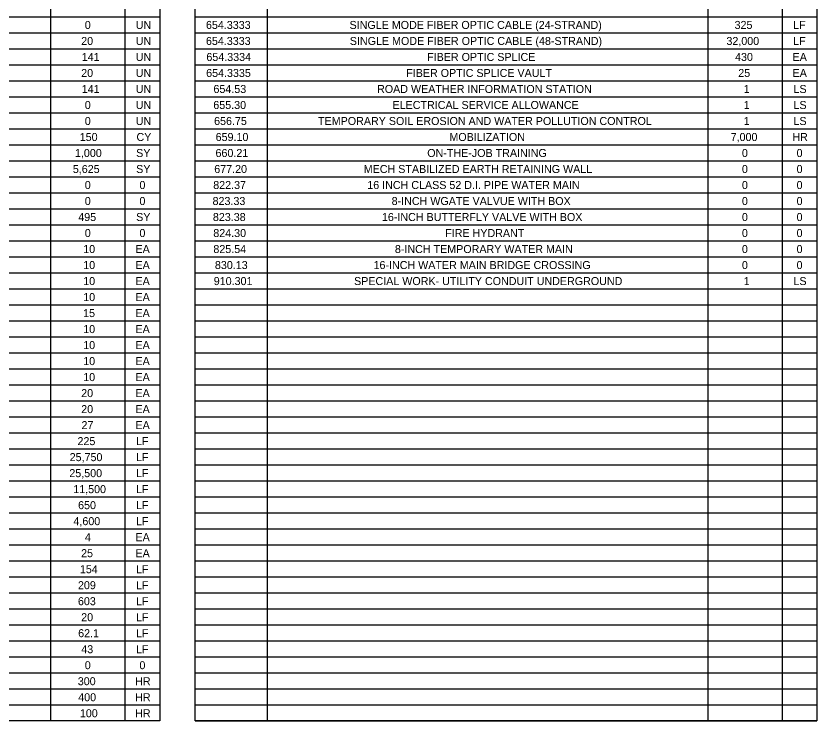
# Model space of a CAD drawing. Extents: x -18.7 to 5.6, y -2.7 to 5.1.
# Drawn here: x 4.632 to 5.617, y 0.019 to 0.886 of the extents above; entities that cross this region are included whole.
import ezdxf

# ---------------------------------------------------------------- set-up
doc = ezdxf.new("R2010")
doc.units = 0
doc.layers.add('ANNOTATION', color=7, linetype='Continuous')
doc.layers.add('BORDER', color=7, linetype='Continuous')

msp = doc.modelspace()

# ---------------------------------------------------------------- linework, layer by layer
at = {"layer": 'BORDER'}
for p, q in [((4.67472, 1.73155), (4.67472, 0.01886)), ((4.76611, 1.73155), (4.76611, 0.01886)), ((4.94124, 1.73155), (4.94124, 0.01886)), ((5.48258, 1.73155), (5.48258, 0.01886)), ((5.57397, 1.73155), (5.57397, 0.01886)), ((3.9448, 0.88505), (4.8091, 0.88505)), ((4.85265, 0.88505), (5.61696, 0.88505)), ((3.9448, 0.86536), (4.8091, 0.86536)), ((4.85265, 0.86536), (5.61696, 0.86536)), ((3.9448, 0.84568), (4.8091, 0.84568)), ((4.85265, 0.84568), (5.61696, 0.84568)), ((3.9448, 0.82599), (4.8091, 0.82599)), ((4.85265, 0.82599), (5.61696, 0.82599)), ((3.9448, 0.8063), (4.8091, 0.8063)), ((4.85265, 0.8063), (5.61696, 0.8063)), ((3.9448, 0.78662), (4.8091, 0.78662)), ((4.85265, 0.78662), (5.61696, 0.78662)), ((3.9448, 0.76693), (4.8091, 0.76693)), ((4.85265, 0.76693), (5.61696, 0.76693)), ((3.9448, 0.74725), (4.8091, 0.74725)), ((4.85265, 0.74725), (5.61696, 0.74725)), ((3.9448, 0.72756), (4.8091, 0.72756)), ((4.85265, 0.72756), (5.61696, 0.72756)), ((3.9448, 0.70787), (4.8091, 0.70787)), ((4.85265, 0.70787), (5.61696, 0.70787)), ((3.9448, 0.68819), (4.8091, 0.68819)), ((4.85265, 0.68819), (5.61696, 0.68819)), ((3.9448, 0.6685), (4.8091, 0.6685)), ((4.85265, 0.6685), (5.61696, 0.6685)), ((3.9448, 0.64882), (4.8091, 0.64882)), ((4.85265, 0.64882), (5.61696, 0.64882)), ((3.9448, 0.62913), (4.8091, 0.62913)), ((4.85265, 0.62913), (5.61696, 0.62913)), ((3.9448, 0.60944), (4.8091, 0.60944)), ((4.85265, 0.60944), (5.61696, 0.60944)), ((3.9448, 0.58976), (4.8091, 0.58976)), ((4.85265, 0.58976), (5.61696, 0.58976)), ((3.9448, 0.57007), (4.8091, 0.57007)), ((4.85265, 0.57007), (5.61696, 0.57007)), ((3.9448, 0.55039), (4.8091, 0.55039)), ((4.85265, 0.55039), (5.61696, 0.55039)), ((3.9448, 0.5307), (4.8091, 0.5307)), ((4.85265, 0.5307), (5.61696, 0.5307)), ((3.9448, 0.51101), (4.8091, 0.51101)), ((4.85265, 0.51101), (5.61696, 0.51101)), ((3.9448, 0.49133), (4.8091, 0.49133)), ((4.85265, 0.49133), (5.61696, 0.49133)), ((3.9448, 0.47164), (4.8091, 0.47164)), ((4.85265, 0.47164), (5.61696, 0.47164)), ((3.97991, 0.45196), (4.8091, 0.45196)), ((4.85265, 0.45196), (5.61696, 0.45196)), ((3.9448, 0.43227), (4.8091, 0.43227)), ((4.85265, 0.43227), (5.61696, 0.43227)), ((3.9448, 0.41258), (4.8091, 0.41258)), ((4.85265, 0.41258), (5.61696, 0.41258)), ((3.9448, 0.3929), (4.8091, 0.3929)), ((4.85265, 0.3929), (5.61696, 0.3929)), ((3.9448, 0.37321), (4.8091, 0.37321)), ((4.85265, 0.37321), (5.61696, 0.37321)), ((3.9448, 0.35353), (4.8091, 0.35353)), ((4.85265, 0.35353), (5.61696, 0.35353)), ((3.9448, 0.33384), (4.8091, 0.33384)), ((4.85265, 0.33384), (5.61696, 0.33384)), ((3.9448, 0.31415), (4.8091, 0.31415)), ((4.85265, 0.31415), (5.61696, 0.31415)), ((3.9448, 0.29447), (4.8091, 0.29447)), ((4.85265, 0.29447), (5.61696, 0.29447)), ((3.9448, 0.27478), (4.8091, 0.27478)), ((4.85265, 0.27478), (5.61696, 0.27478)), ((3.9448, 0.2551), (4.8091, 0.2551)), ((4.85265, 0.2551), (5.61696, 0.2551)), ((3.9448, 0.23541), (4.8091, 0.23541)), ((4.85265, 0.23541), (5.61696, 0.23541)), ((3.9448, 0.21572), (4.8091, 0.21572)), ((4.85265, 0.21572), (5.61696, 0.21572)), ((3.9448, 0.19604), (4.8091, 0.19604)), ((4.85265, 0.19604), (5.61696, 0.19604)), ((3.9448, 0.17635), (4.8091, 0.17635)), ((4.85265, 0.17635), (5.61696, 0.17635)), ((3.9448, 0.15667), (4.8091, 0.15667)), ((4.85265, 0.15667), (5.61696, 0.15667)), ((3.9448, 0.13698), (4.8091, 0.13698)), ((4.85265, 0.13698), (5.61696, 0.13698)), ((3.9448, 0.11729), (4.8091, 0.11729)), ((4.85265, 0.11729), (5.61696, 0.11729)), ((3.9448, 0.09761), (4.8091, 0.09761)), ((4.85265, 0.09761), (5.61696, 0.09761)), ((3.9448, 0.07792), (4.8091, 0.07792)), ((4.85265, 0.07792), (5.61696, 0.07792)), ((3.9448, 0.05824), (4.8091, 0.05824)), ((4.85265, 0.05824), (5.61696, 0.05824)), ((3.9448, 0.03855), (4.8091, 0.03855)), ((4.85265, 0.03855), (5.61696, 0.03855)), ((4.85265, 0.01886), (5.61696, 0.01886))]:
    msp.add_line(p, q, dxfattribs=at)
for points in [[(3.9448, 1.75123), (4.8091, 1.75123), (4.8091, 0.01886), (3.9448, 0.01886)], [(4.85265, 1.75123), (5.61696, 1.75123), (5.61696, 0.01886), (4.85265, 0.01886)]]:
    msp.add_lwpolyline(points, close=True, dxfattribs=at)

# ---------------------------------------------------------------- texts
at = {"layer": 'ANNOTATION'}
for s, height, p in [('0', 0.00984, (4.71684, 0.86996)), ('UN', 0.009843, (4.77947, 0.86996)), ('654.3333', 0.009843, (4.86582, 0.86996)), ('SINGLE MODE FIBER OPTIC CABLE (24-STRAND)', 0.009843, (5.04234, 0.86996)), ('325', 0.009843, (5.51567, 0.86996)), ('LF', 0.009843, (5.58764, 0.86996)), ('20', 0.009843, (4.71242, 0.85027)), ('UN', 0.009843, (4.77947, 0.85027)), ('654.3333', 0.009843, (4.86582, 0.85027)), ('SINGLE MODE FIBER OPTIC CABLE (48-STRAND)', 0.009843, (5.04265, 0.85027)), ('32,000', 0.009843, (5.50564, 0.85027)), ('LF', 0.009843, (5.58764, 0.85027)), ('141', 0.009843, (4.71312, 0.83059)), ('UN', 0.009843, (4.77947, 0.83059)), ('654.3334', 0.009843, (4.86632, 0.83059)), ('FIBER OPTIC SPLICE', 0.009843, (5.13768, 0.83059)), ('430', 0.009843, (5.51625, 0.83059)), ('EA', 0.009843, (5.58701, 0.83059)), ('20', 0.009843, (4.71242, 0.8109)), ('UN', 0.009843, (4.77947, 0.8109)), ('654.3335', 0.009843, (4.86605, 0.8109)), ('FIBER OPTIC SPLICE VAULT', 0.009843, (5.11199, 0.8109)), ('25', 0.009843, (5.52016, 0.8109)), ('EA', 0.009843, (5.58701, 0.8109)), ('141', 0.009843, (4.71312, 0.79121)), ('UN', 0.009843, (4.77947, 0.79121)), ('654.53', 0.009843, (4.87503, 0.79121)), ('ROAD WEATHER INFORMATION STATION', 0.009843, (5.07615, 0.79121)), ('1', 0.00984, (5.52687, 0.79121)), ('LS', 0.009843, (5.58806, 0.79121)), ('0', 0.00984, (4.71684, 0.77153)), ('UN', 0.009843, (4.77947, 0.77153)), ('655.30', 0.009843, (4.87484, 0.77153)), ('ELECTRICAL SERVICE ALLOWANCE', 0.009843, (5.09515, 0.77153)), ('1', 0.00984, (5.52687, 0.77153)), ('LS', 0.009843, (5.58806, 0.77153)), ('0', 0.00984, (4.71684, 0.75184)), ('UN', 0.009843, (4.77947, 0.75184)), ('656.75', 0.009843, (4.87581, 0.75184)), ('TEMPORARY SOIL EROSION AND WATER POLLUTION CONTROL', 0.009843, (5.00361, 0.75184)), ('1', 0.00984, (5.52687, 0.75184)), ('LS', 0.009843, (5.58806, 0.75184)), ('150', 0.009843, (4.71064, 0.73216)), ('CY', 0.009843, (4.7804, 0.73216)), ('659.10', 0.009843, (4.87771, 0.73216)), ('MOBILIZATION', 0.009843, (5.16508, 0.73216)), ('7,000', 0.009843, (5.51083, 0.73216)), ('HR', 0.009843, (5.58665, 0.73216)), ('1,000', 0.009843, (4.70476, 0.71247)), ('SY', 0.009843, (4.78001, 0.71247)), ('660.21', 0.009843, (4.87755, 0.71247)), ('ON-THE-JOB TRAINING', 0.009843, (5.13783, 0.71247)), ('0', 0.00984, (5.5247, 0.71247)), ('0', 0.00984, (5.5919, 0.71247)), ('5,625', 0.009843, (4.70216, 0.69278)), ('SY', 0.009843, (4.78001, 0.69278)), ('677.20', 0.009843, (4.876, 0.69278)), ('MECH STABILIZED EARTH RETAINING WALL', 0.009843, (5.05978, 0.69278)), ('0', 0.00984, (5.5247, 0.69278)), ('0', 0.00984, (5.5919, 0.69278)), ('0', 0.00984, (4.71684, 0.6731)), ('0', 0.00984, (4.78404, 0.6731)), ('822.37', 0.009843, (4.87476, 0.6731)), ('16 INCH CLASS 52 D.I. PIPE WATER MAIN', 0.009843, (5.06412, 0.6731)), ('0', 0.00984, (5.5247, 0.6731)), ('0', 0.00984, (5.5919, 0.6731)), ('0', 0.00984, (4.71684, 0.65341)), ('0', 0.00984, (4.78404, 0.65341)), ('823.33', 0.009843, (4.87395, 0.65341)), ('8-INCH WGATE VALVUE WITH BOX', 0.009843, (5.09409, 0.65341)), ('0', 0.00984, (5.5247, 0.65341)), ('0', 0.00984, (5.5919, 0.65341)), ('495', 0.009843, (4.70882, 0.63373)), ('SY', 0.009843, (4.78001, 0.63373)), ('823.38', 0.009843, (4.87434, 0.63373)), ('16-INCH BUTTERFLY VALVE WITH BOX', 0.009843, (5.08213, 0.63373)), ('0', 0.00984, (5.5247, 0.63373)), ('0', 0.00984, (5.5919, 0.63373)), ('0', 0.00984, (4.71684, 0.61404)), ('0', 0.00984, (4.78404, 0.61404)), ('824.30', 0.009843, (4.87484, 0.61404)), ('FIRE HYDRANT', 0.009843, (5.15994, 0.61404)), ('0', 0.00984, (5.5247, 0.61404)), ('0', 0.00984, (5.5919, 0.61404)), ('10', 0.009843, (4.7149, 0.59435)), ('EA', 0.009843, (4.77916, 0.59435)), ('825.54', 0.009843, (4.87492, 0.59435)), ('8-INCH TEMPORARY WATER MAIN', 0.009843, (5.09809, 0.59435)), ('0', 0.00984, (5.5247, 0.59435)), ('0', 0.00984, (5.5919, 0.59435)), ('10', 0.009843, (4.7149, 0.57467)), ('EA', 0.009843, (4.77916, 0.57467)), ('830.13', 0.009843, (4.87682, 0.57467)), ('16-INCH WATER MAIN BRIDGE CROSSING', 0.009843, (5.07181, 0.57467)), ('0', 0.00984, (5.5247, 0.57467)), ('0', 0.00984, (5.5919, 0.57467)), ('10', 0.009843, (4.7149, 0.55498)), ('EA', 0.009843, (4.77916, 0.55498)), ('910.301', 0.009843, (4.87539, 0.55498)), ('SPECIAL WORK- UTILITY CONDUIT UNDERGROUND', 0.009843, (5.04789, 0.55498)), ('1', 0.00984, (5.52687, 0.55498)), ('LS', 0.009843, (5.58806, 0.55498)), ('10', 0.009843, (4.7149, 0.5353)), ('EA', 0.009843, (4.77916, 0.5353)), ('15', 0.009843, (4.71479, 0.51561)), ('EA', 0.009843, (4.77916, 0.51561)), ('10', 0.009843, (4.7149, 0.49592)), ('EA', 0.009843, (4.77916, 0.49592)), ('10', 0.009843, (4.7149, 0.47624)), ('EA', 0.009843, (4.77916, 0.47624)), ('10', 0.009843, (4.7149, 0.45655)), ('EA', 0.009843, (4.77916, 0.45655)), ('10', 0.009843, (4.7149, 0.43687)), ('EA', 0.009843, (4.77916, 0.43687)), ('20', 0.009843, (4.71242, 0.41718)), ('EA', 0.009843, (4.77916, 0.41718)), ('20', 0.009843, (4.71242, 0.39749)), ('EA', 0.009843, (4.77916, 0.39749)), ('27', 0.009843, (4.71281, 0.37781)), ('EA', 0.009843, (4.77916, 0.37781)), ('225', 0.009843, (4.70789, 0.35812)), ('LF', 0.009843, (4.77978, 0.35812)), ('25,750', 0.009843, (4.69825, 0.33844)), ('LF', 0.009843, (4.77978, 0.33844)), ('25,500', 0.009843, (4.69786, 0.31875)), ('LF', 0.009843, (4.77978, 0.31875)), ('11,500', 0.009843, (4.70267, 0.29906)), ('LF', 0.009843, (4.77978, 0.29906)), ('650', 0.009843, (4.70863, 0.27938)), ('LF', 0.009843, (4.77978, 0.27938)), ('4,600', 0.009843, (4.7029, 0.25969)), ('LF', 0.009843, (4.77978, 0.25969)), ('4', 0.00984, (4.71699, 0.24001)), ('EA', 0.009843, (4.77916, 0.24001)), ('25', 0.009843, (4.71231, 0.22032)), ('EA', 0.009843, (4.77916, 0.22032)), ('154', 0.009843, (4.7108, 0.20063)), ('LF', 0.009843, (4.77978, 0.20063)), ('209', 0.009843, (4.70847, 0.18095)), ('LF', 0.009843, (4.77978, 0.18095)), ('603', 0.009843, (4.70843, 0.16126)), ('LF', 0.009843, (4.77978, 0.16126)), ('20', 0.009843, (4.71242, 0.14158)), ('LF', 0.009843, (4.77978, 0.14158)), ('62.1', 0.009843, (4.70871, 0.12189)), ('LF', 0.009843, (4.77978, 0.12189)), ('43', 0.009843, (4.71254, 0.1022)), ('LF', 0.009843, (4.77978, 0.1022)), ('0', 0.00984, (4.71684, 0.08252)), ('0', 0.00984, (4.78404, 0.08252)), ('300', 0.009843, (4.70824, 0.06283)), ('HR', 0.009843, (4.77879, 0.06283)), ('400', 0.009843, (4.70878, 0.04315)), ('HR', 0.009843, (4.77879, 0.04315)), ('100', 0.009843, (4.7108, 0.02346)), ('HR', 0.009843, (4.77879, 0.02346))]:
    msp.add_text(s, height=height, dxfattribs=at).set_placement(p)

doc.saveas('drawing.dxf')
